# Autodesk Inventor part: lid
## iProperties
Shininess: 64.0
Length Units: 11269
Angle Units: 11279
Time Units: 11290
Mass Units: 11283
Length Display Precision: 3
Angle Display Precision: 2
Compacted: True
Part Number: lid
Document SubType Name: Modeling
Created: 2004-07
Designer: Peter
Manufacturer: Standard
Standards Organization: Custom
Density: 0.0
Volumn: 0.0
Area: 0.0
PropertySet Name: Model Information
Control State: 0
Master: False
Checked Out: False
Author: Peter
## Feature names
1. Revolution1
